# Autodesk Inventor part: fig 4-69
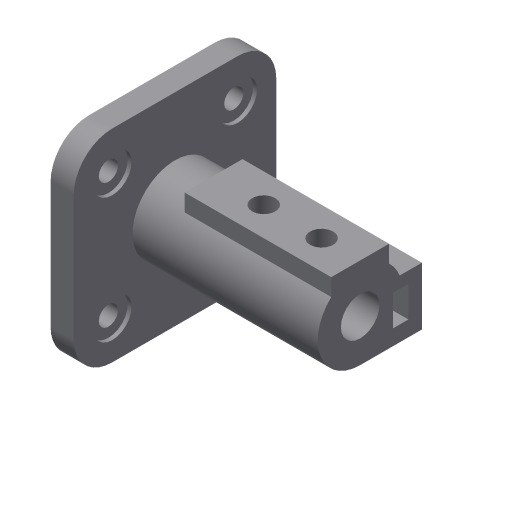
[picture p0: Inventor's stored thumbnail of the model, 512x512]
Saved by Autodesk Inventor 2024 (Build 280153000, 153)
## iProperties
Created: 2001-12
Part Number: fig 4-69
Document SubType Name: Modeling
Designer: Renu Muthoo
Density: 1 g/cm^3
Material: Generic
Appearance: Default
Control State: 0
Master: False
Checked Out: False
Shininess: 77.0
Length Units: 11269
Angle Units: 11279
Time Units: 11290
Mass Units: 11283
Length Display Precision: 3
Angle Display Precision: 2
Density: 0.0
Volumn: 0.0
Area: 0.0
PropertySet Name: Model Information
Author: Renu Muthoo
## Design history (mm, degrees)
sketch "Sketch2"
  geometry: L1 (24.44, 30.488)-(-40.56, 30.488); L2 (-60.56, 10.488)-(-60.56, -54.512); L3 (-40.56, -74.512)-(24.44, -74.512); L4 (44.44, -54.512)-(44.44, 10.488); A1 r 20 centre (24.44, 10.488) between (44.44, 10.488) and (24.44, 30.488); A2 r 20 centre (-40.56, 10.488) between (-40.56, 30.488) and (-60.56, 10.488); A3 r 20 centre (-40.56, -54.512) between (-60.56, -54.512) and (-40.56, -74.512); A4 r 20 centre (24.44, -54.512) between (24.44, -74.512) and (44.44, -54.512); 2 further points
  constraints: 8 end point, 8 point on circle, 8 tangent, 4 centre point, 4 point on line, 3 equal radius, 2 parallel, 2 perpendicular, 1 horizontal
  dimensions: "d1" = 20 radius of A1; "d2" = 105 distance between parallel lines of L2 L4
extrude "Extrusion1" new body sketch "Sketch2" distance "d3" = 12; taper "d4" = 0 deg
sketch "Sketch3"
  geometry: A1 r 20 centre (-24.44, 10.488) between (-24.44, 30.488) and (-44.44, 10.488) reference; A2 r 20 centre (-24.44, -54.512) between (-44.44, -54.512) and (-24.44, -74.512) reference; A3 r 20 centre (40.56, -54.512) between (40.56, -74.512) and (60.56, -54.512) reference; A4 r 20 centre (40.56, 10.488) between (60.56, 10.488) and (40.56, 30.488) reference
hole "Hole1" sketch "Sketch3" diameter "d5" = 10; stored, may be unused: countersink angle "d9" = 82 deg, drill point angle "d11" = 118 deg; dims "d6" = 6, "d7" = 20, "d8" = 2, "d10" = 8
sketch "Sketch4"
  geometry: L1 (-24.44, 30.488)-(40.56, 30.488) reference; L2 (-44.44, -54.512)-(-44.44, 10.488) reference; C1 r 22 at (8.06, -22.012)
  constraints: 1 centre point
  dimensions: "d12" = 52.5 distance from line of L2 C1.centre; "d13" = 52.5 distance from line of L1 C1.centre; "d14" = 44 diameter of C1
extrude "Extrusion2" join sketch "Sketch4" distance "d15" = 96; taper "d16" = 0 deg
sketch "Sketch5"
  geometry: L1 (-15, 16.093)-(15, 16.093); L2 (15, 16.093)-(15, 25); L3 (15, 25)-(-15, 25); L4 (-15, 25)-(-15, 16.093); 1 further point
  constraints: 8 end point, 2 parallel, 1 horizontal, 1 perpendicular, 2 other
  dimensions: "d17" = 30 distance of L2.end L3.end; "d18" = 25 distance from line of point (0, 0) L3; "d19" = 15 distance from line of point (0, 0) L4
extrude "Extrusion3" join sketch "Sketch5" distance "d20" = 76; taper "d21" = 0 deg
sketch "Sketch6"
  geometry: L1 (8, -44.012)-(40.06, -44.012); L2 (40.06, -44.012)-(40.06, -14.012); L3 (40.06, -14.012)-(8, -14.012); L4 (8, -14.012)-(8, -44.012); A1 r 22 centre (8.06, -22.012) between (-6.94, -5.918) and (23.06, -5.918) reference
  constraints: 8 end point, 2 parallel, 1 horizontal, 1 perpendicular, 1 tangent
  dimensions: "d22" = 32 distance from line of A1.centre L2; "d23" = 30 distance of L1.end L2.end
extrude "Extrusion4" join sketch "Sketch6" distance "d24" = 57; taper "d25" = 0 deg
sketch "Sketch7"
  geometry: L1 (25.06, -20.012)-(33.06, -20.012); L2 (33.06, -20.012)-(33.06, -36.012); L3 (33.06, -36.012)-(25.06, -36.012); L4 (25.06, -36.012)-(25.06, -20.012); A1 r 22 centre (8.06, -22.012) between (-6.94, -5.918) and (8, -44.012) reference
  constraints: 8 end point, 2 parallel, 1 horizontal, 1 perpendicular
  dimensions: "d26" = 8 distance of L2.end L3.end; "d27" = 16 distance of L1.end L2.end; "d28" = 25 distance from line of A1.centre L2; "d29" = 2 vertical distance of A1.centre L1.start
extrude "Extrusion5" cut sketch "Sketch7" distance "d30" = 35; taper "d31" = 0 deg
sketch "Sketch8"
  geometry: A1 r 22 centre (8.06, -22.012) between (-6.94, -5.918) and (8, -44.012) reference
hole "Hole2" sketch "Sketch8" diameter "d32" = 20; stored, may be unused: countersink angle "d36" = 82 deg, drill point angle "d38" = 0 deg; dims "d33" = 6, "d34" = 20, "d35" = 2, "d37" = 96
sketch "Sketch9"
  geometry: L1 (0, 0)-(0, 76) reference; L2 (30, 0)-(0, 0) reference; 2 further points
  dimensions: "d39" = 20 distance from line of L2 point (15, 20); "d40" = 15 distance from line of L1 point (15, 20); "d41" = 30 distance of point (15, 50) point (15, 20)
hole "Hole3" sketch "Sketch9" at (15, 20), (15, 50) diameter "d42" = 12; stored, may be unused: countersink angle "d46" = 82 deg, drill point angle "d48" = 0 deg; dims "d43" = 6, "d44" = 20, "d45" = 2, "d47" = 25
sketch "Sketch10"
  geometry: L1 (30, 0)-(0, 0) reference; L2 (30, 0)-(30, 57) reference; 2 further points
  dimensions: "d49" = 15 distance from line of L1 point (15, 15); "d50" = 15 distance from line of L2 point (15, 15); "d51" = 22 distance of point (15, 37) point (15, 15)
hole "Hole4" sketch "Sketch10" at (15, 15), (15, 37) diameter "d52" = 10; stored, may be unused: countersink angle "d56" = 82 deg, drill point angle "d58" = 0 deg; dims "d53" = 6, "d54" = 20, "d55" = 2, "d57" = 7
body "Solid1"
node "Sketch1"
